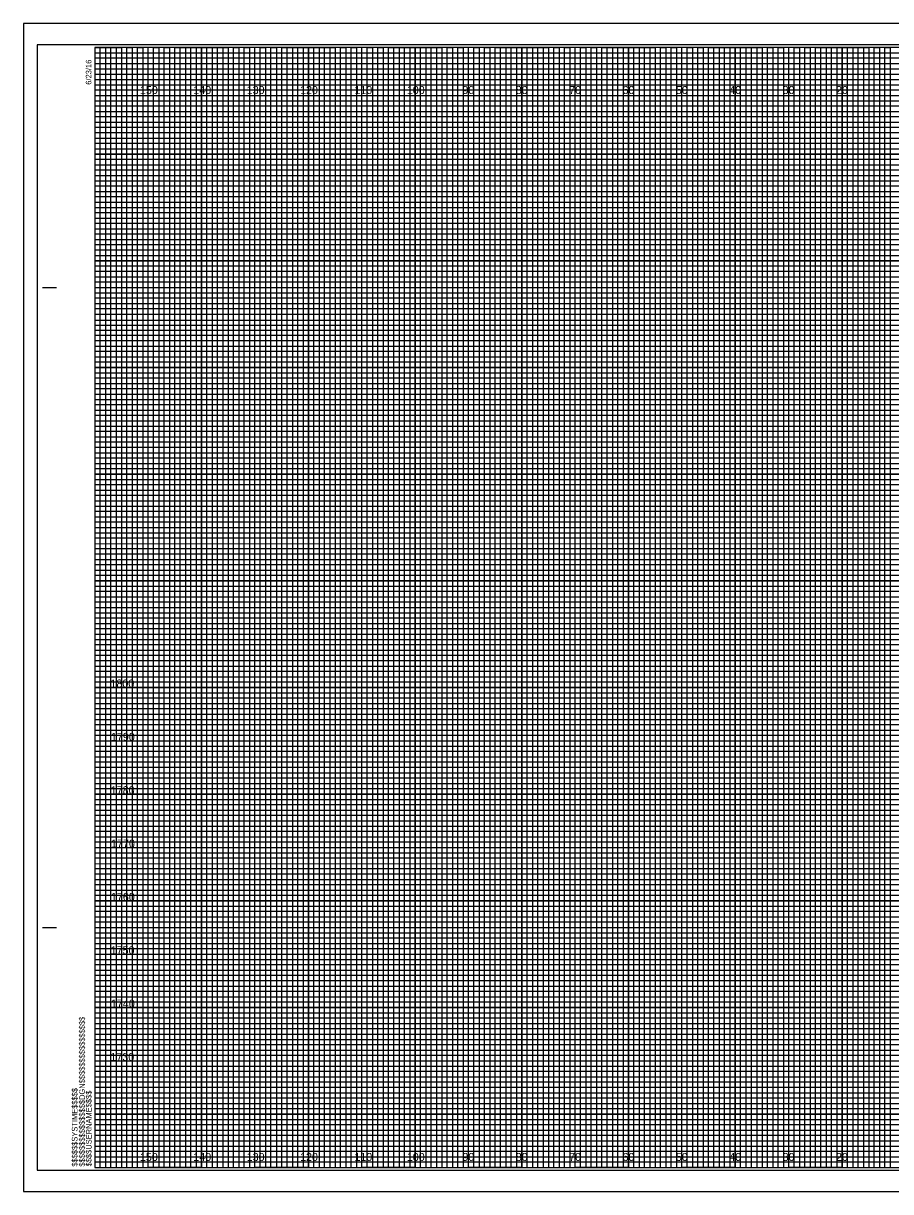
# Model space of a CAD drawing. Extents: x 570 to 907, y -9 to 870.
# Drawn here: x 570.4 to 732.9, y 650.6 to 869.6 of the extents above; entities that cross this region are included whole.
import ezdxf

# ---------------------------------------------------------------- set-up
doc = ezdxf.new("R2010")
doc.units = 0
for name, color, linetype in [('Prop XS Earthwork Shape', 7, 'Continuous'), ('Raster_Level_0', 7, 'Continuous'), ('Scratch_Level_3', 7, 'Continuous'), ('Sheet Cross Section CELL', 7, 'Continuous'), ('Sheet Cross Section Grid Middle CELL', 7, 'Continuous'), ('Sheet Cross Section Grid Minor 1 CELL', 7, 'Continuous'), ('Sheet Cross Section Grid Minor 2 CELL', 7, 'Continuous'), ('Sheet Cutting Line CELL', 7, 'Continuous'), ('Sheet DOT Grid CELL', 7, 'Continuous'), ('Sheet Plot Border Inside CELL', 7, 'Continuous'), ('Sheet Plot Border Outside CELL', 7, 'Continuous')]:
    doc.layers.add(name, color=color, linetype=linetype)

msp = doc.modelspace()

# ---------------------------------------------------------------- linework, layer by layer
at = {"layer": 'Prop XS Earthwork Shape'}
for p, q in [((593.77, 865.14), (583.77, 865.14)), ((593.77, 655.14), (593.77, 865.14)), ((613.77, 865.14), (603.77, 865.14)), ((603.77, 865.14), (603.77, 655.14)), ((613.77, 655.14), (613.77, 865.14)), ((633.77, 865.14), (623.77, 865.14)), ((623.77, 865.14), (623.77, 655.14)), ((633.77, 655.14), (633.77, 865.14)), ((653.77, 865.14), (643.77, 865.14)), ((643.77, 865.14), (643.77, 655.14)), ((653.77, 655.14), (653.77, 865.14)), ((673.77, 865.14), (663.77, 865.14)), ((663.77, 865.14), (663.77, 655.14)), ((673.77, 655.14), (673.77, 865.14)), ((693.77, 865.14), (683.77, 865.14)), ((683.77, 865.14), (683.77, 655.14)), ((693.77, 655.14), (693.77, 865.14)), ((713.77, 865.14), (703.77, 865.14)), ((703.77, 865.14), (703.77, 655.14)), ((713.77, 655.14), (713.77, 865.14)), ((733.77, 865.14), (723.77, 865.14)), ((723.77, 865.14), (723.77, 655.14)), ((603.77, 655.14), (593.77, 655.14)), ((623.77, 655.14), (613.77, 655.14)), ((643.77, 655.14), (633.77, 655.14)), ((663.77, 655.14), (653.77, 655.14)), ((683.77, 655.14), (673.77, 655.14)), ((703.77, 655.14), (693.77, 655.14)), ((723.77, 655.14), (713.77, 655.14))]:
    msp.add_line(p, q, dxfattribs=at)
for points in [[(583.77, 855.14), (903.77, 855.14), (903.77, 845.14), (583.77, 845.14)], [(583.77, 835.14), (903.77, 835.14), (903.77, 825.14), (583.77, 825.14)], [(583.77, 815.14), (903.77, 815.14), (903.77, 805.14), (583.77, 805.14)], [(583.77, 795.14), (903.77, 795.14), (903.77, 785.14), (583.77, 785.14)], [(583.77, 775.14), (903.77, 775.14), (903.77, 765.14), (583.77, 765.14)], [(583.77, 755.14), (903.77, 755.14), (903.77, 745.14), (583.77, 745.14)], [(583.77, 735.14), (903.77, 735.14), (903.77, 725.14), (583.77, 725.14)], [(583.77, 715.14), (903.77, 715.14), (903.77, 705.14), (583.77, 705.14)], [(583.77, 695.14), (903.77, 695.14), (903.77, 685.14), (583.77, 685.14)], [(583.77, 675.14), (903.77, 675.14), (903.77, 665.14), (583.77, 665.14)]]:
    msp.add_lwpolyline(points, dxfattribs=at)
at = {"layer": 'Sheet Cross Section CELL'}
for p, q in [((573.97, 820.14), (576.47, 820.14)), ((574.07, 820.14), (576.57, 820.14)), ((573.97, 700.14), (576.47, 700.14)), ((574.07, 700.14), (576.57, 700.14)), ((583.77, 655.14), (583.77, 655.14)), ((583.77, 655.14), (583.77, 655.14)), ((583.77, 655.14), (583.77, 655.14)), ((583.77, 655.14), (583.77, 655.14)), ((583.77, 655.14), (583.77, 655.14)), ((583.77, 655.14), (583.77, 655.14)), ((583.77, 655.14), (583.77, 655.14))]:
    msp.add_line(p, q, dxfattribs=at)
msp.add_lwpolyline([(903.77, 865.14), (583.77, 865.14), (583.77, 655.14), (903.77, 655.14)], close=True, dxfattribs=at)
at = {"layer": 'Sheet Cross Section Grid Middle CELL'}
for points in [[(583.77, 865.14), (588.77, 865.14), (588.77, 655.14), (598.77, 655.14), (598.77, 865.14), (608.77, 865.14), (608.77, 655.14), (618.77, 655.14), (618.77, 865.14), (628.77, 865.14), (628.77, 655.14), (638.77, 655.14), (638.77, 865.14), (648.77, 865.14), (648.77, 655.14), (658.77, 655.14), (658.77, 865.14), (668.77, 865.14), (668.77, 655.14), (678.77, 655.14), (678.77, 865.14), (688.77, 865.14), (688.77, 655.14), (698.77, 655.14), (698.77, 865.14), (708.77, 865.14), (708.77, 655.14), (718.77, 655.14), (718.77, 865.14), (728.77, 865.14), (728.77, 655.14), (738.77, 655.14)], [(583.77, 860.14), (858.77, 860.14)], [(583.77, 840.14), (903.77, 840.14), (903.77, 850.14), (583.77, 850.14)], [(583.77, 820.14), (903.77, 820.14), (903.77, 830.14), (583.77, 830.14)], [(583.77, 800.14), (903.77, 800.14), (903.77, 810.14), (583.77, 810.14)], [(583.77, 780.14), (903.77, 780.14), (903.77, 790.14), (583.77, 790.14)], [(583.77, 760.14), (903.77, 760.14), (903.77, 770.14), (583.77, 770.14)], [(583.77, 740.14), (903.77, 740.14), (903.77, 750.14), (583.77, 750.14)], [(583.77, 720.14), (903.77, 720.14), (903.77, 730.14), (583.77, 730.14)], [(583.77, 700.14), (903.77, 700.14), (903.77, 710.14), (583.77, 710.14)], [(583.77, 680.14), (903.77, 680.14), (903.77, 690.14), (583.77, 690.14)], [(583.77, 660.14), (903.77, 660.14), (903.77, 670.14), (583.77, 670.14)]]:
    msp.add_lwpolyline(points, dxfattribs=at)
at = {"layer": 'Sheet Cross Section Grid Minor 1 CELL'}
for p, q in [((583.77, 864.14), (843.77, 864.14)), ((843.77, 863.12), (583.77, 863.12)), ((583.77, 863.12), (583.77, 862.14)), ((583.77, 862.14), (843.77, 862.14)), ((843.77, 861.03), (583.77, 861.03)), ((583.77, 861.03), (583.77, 859.14)), ((583.77, 859.14), (903.77, 859.14))]:
    msp.add_line(p, q, dxfattribs=at)
for points in [[(583.77, 858.14), (853.77, 858.14), (903.77, 858.14), (903.77, 857.14), (583.77, 857.14)], [(583.77, 856.14), (903.77, 856.14), (903.77, 854.14), (583.77, 854.14)], [(583.77, 853.14), (903.77, 853.14), (903.77, 852.14), (583.77, 852.12)], [(583.77, 851.14), (903.77, 851.14), (903.77, 849.14), (583.77, 849.14)], [(583.77, 848.14), (903.77, 848.14), (903.77, 847.14), (583.77, 847.14)], [(583.77, 846.14), (903.77, 846.14), (903.77, 844.14), (583.77, 844.14)], [(583.77, 843.14), (903.77, 843.14), (903.77, 842.14), (583.77, 842.14)], [(583.77, 841.14), (903.77, 841.14), (903.77, 839.14), (583.77, 839.14)], [(583.77, 838.14), (903.77, 838.14), (903.77, 837.14), (583.77, 837.14)], [(583.77, 836.14), (903.77, 836.14), (903.77, 834.14), (583.77, 834.14)], [(583.77, 833.14), (903.77, 833.14), (903.77, 832.14), (583.77, 832.14)], [(583.77, 831.14), (903.77, 831.14), (903.77, 829.09), (903.77, 828.14), (903.77, 827.14), (583.77, 827.14)], [(583.77, 829.14), (903.77, 829.14), (903.77, 828.14), (583.77, 828.14)], [(583.77, 826.14), (903.77, 826.14), (903.77, 824.14), (583.77, 824.17)], [(583.77, 824.17), (903.77, 824.14), (903.77, 823.14), (583.77, 823.14)], [(583.77, 822.14), (903.77, 822.14), (903.77, 821.14), (583.77, 821.14)], [(583.77, 819.14), (903.77, 819.14), (903.77, 818.14), (583.77, 818.14)], [(583.77, 817.14), (903.77, 817.14), (903.77, 816.14), (583.77, 816.14)], [(583.7, 814.03), (903.77, 814.03), (903.77, 813.02), (583.7, 813.02)], [(583.77, 812.14), (903.77, 812.14), (903.77, 811.14), (583.77, 811.14)], [(583.77, 809.14), (903.77, 809.14), (903.77, 808.14), (583.77, 808.14)], [(583.77, 807.14), (903.77, 807.14), (903.77, 806.14), (583.77, 806.14)], [(583.77, 804.14), (903.77, 804.14), (903.77, 803.14), (583.77, 803.14)], [(583.77, 802.14), (903.77, 802.14), (903.77, 801.14), (583.77, 801.14)], [(583.77, 799.14), (903.77, 799.14), (903.77, 798.14), (583.77, 798.14)], [(583.77, 797.14), (903.77, 797.14), (903.77, 796.14), (583.77, 796.14)], [(583.77, 794.14), (903.77, 794.14), (903.76, 793.12), (583.77, 793.14)], [(583.77, 792.14), (903.77, 792.14), (903.77, 791.14), (583.77, 791.14)], [(583.77, 789.14), (903.77, 789.14), (903.77, 788.14), (583.77, 788.14)], [(583.77, 787.14), (903.77, 787.14), (903.77, 786.14), (583.77, 786.14)], [(583.77, 784.14), (903.77, 784.14), (903.77, 783.14), (583.77, 783.14)], [(583.77, 782.14), (903.77, 782.14), (903.77, 781.14), (583.77, 781.14)], [(583.77, 779.14), (903.77, 779.14), (903.77, 778.14), (583.77, 778.14)], [(583.77, 777.14), (903.77, 777.14), (903.77, 776.14), (583.77, 776.14)], [(583.77, 774.14), (903.77, 774.14), (903.77, 773.14), (583.77, 773.14)], [(583.77, 772.13), (903.84, 772.05), (903.77, 771.14), (583.77, 771.14)], [(583.77, 769.14), (903.77, 769.14), (903.77, 768.14), (583.77, 768.14)], [(583.77, 767.14), (903.77, 767.14), (903.77, 766.14), (583.77, 766.14)], [(583.77, 764.14), (903.77, 764.14), (903.77, 763.14), (583.77, 763.14)], [(583.77, 762.14), (903.77, 762.14), (903.77, 761.14), (583.77, 761.14)], [(583.77, 759.14), (903.77, 759.14), (903.77, 758.14), (583.77, 758.14)], [(583.77, 757.14), (903.77, 757.14), (903.77, 756.14), (583.77, 756.14)], [(583.77, 754.14), (903.77, 754.14), (903.77, 753.14), (583.77, 753.14)], [(583.77, 752.14), (903.77, 752.14), (903.77, 751.14), (583.77, 751.14)], [(583.77, 749.14), (903.77, 749.14), (903.77, 748.14), (583.77, 748.14)], [(583.77, 747.14), (903.77, 747.14), (903.77, 746.14), (583.77, 746.14)], [(583.77, 744.14), (903.77, 744.14), (903.77, 743.14), (583.77, 743.14)], [(583.77, 742.14), (903.77, 742.14), (903.77, 741.14), (583.77, 741.14)], [(583.77, 739.14), (903.77, 739.14), (903.77, 738.14), (583.77, 738.14)], [(583.77, 737.14), (903.77, 737.14), (903.77, 736.14), (583.77, 736.14)], [(583.77, 734.14), (903.77, 734.14), (903.76, 733.12), (583.77, 733.14)], [(583.77, 732.14), (903.77, 732.14), (903.77, 731.14), (583.77, 731.14)], [(583.77, 729.14), (903.77, 729.14), (903.77, 728.14), (583.77, 728.14)], [(583.77, 727.14), (903.77, 727.14), (903.77, 726.14), (583.77, 726.14)], [(583.77, 724.14), (903.77, 724.14), (903.77, 723.14), (583.77, 723.14)], [(583.77, 722.14), (903.77, 722.14), (903.77, 721.14), (583.77, 721.14)], [(583.77, 719.14), (903.77, 719.14), (903.77, 718.14), (583.77, 718.14)], [(583.77, 717.14), (903.77, 717.14), (903.77, 716.14), (583.77, 716.14)], [(583.77, 714.14), (903.77, 714.14), (903.77, 713.14), (583.77, 713.14)], [(583.77, 712.13), (903.84, 712.05), (903.77, 711.14), (583.77, 711.14)], [(583.77, 709.14), (903.77, 709.14), (903.77, 708.14), (583.77, 708.14)], [(583.77, 707.14), (903.77, 707.14), (903.77, 706.14), (583.77, 706.14)], [(583.77, 704.14), (903.77, 704.14), (903.77, 703.14), (583.77, 703.14)], [(583.77, 702.14), (903.77, 702.14), (903.77, 701.14), (583.77, 701.14)], [(583.77, 699.14), (903.77, 699.14), (903.77, 698.14), (583.77, 698.14)], [(583.77, 697.14), (903.77, 697.14), (903.77, 696.14), (583.77, 696.14)], [(583.77, 694.14), (903.77, 694.14), (903.77, 693.14), (583.77, 693.14)], [(583.77, 692.14), (903.77, 692.14), (903.77, 691.14), (583.77, 691.14)], [(583.77, 689.14), (903.77, 689.14), (903.77, 688.14), (583.77, 688.14)], [(583.77, 687.14), (903.77, 687.14), (903.77, 686.14), (583.77, 686.14)], [(583.77, 684.14), (903.77, 684.14), (903.77, 683.14), (583.77, 683.14)], [(583.77, 682.14), (903.77, 682.14), (903.77, 681.14), (583.77, 681.14)], [(583.77, 679.14), (903.77, 679.14), (903.77, 678.14), (583.77, 678.14)], [(583.77, 677.14), (903.77, 677.14), (903.77, 676.14), (583.77, 676.14)], [(583.77, 674.14), (903.77, 674.14), (903.77, 673.14), (583.77, 673.14)], [(583.77, 672.14), (903.77, 672.14), (903.77, 671.14), (583.77, 671.14)], [(583.77, 669.14), (903.77, 669.14), (903.77, 668.14), (583.77, 668.14)], [(583.77, 667.14), (903.77, 667.14), (903.77, 666.14), (583.77, 666.14)], [(583.77, 664.14), (903.77, 664.14), (903.77, 663.14), (583.77, 663.14)], [(583.77, 662.14), (903.77, 662.14), (903.77, 661.14), (583.77, 661.14)], [(583.77, 659.14), (903.77, 659.14), (903.77, 658.14), (583.77, 658.14)], [(583.77, 657.14), (903.77, 657.14), (903.77, 656.14), (583.77, 656.14)]]:
    msp.add_lwpolyline(points, dxfattribs=at)
at = {"layer": 'Sheet Cross Section Grid Minor 2 CELL'}
for points in [[(583.77, 655.14), (584.77, 655.14), (584.77, 865.14), (585.77, 865.14), (585.77, 655.14)], [(585.77, 655.14), (586.77, 655.14), (586.77, 865.14), (587.77, 865.14), (587.77, 655.14)], [(588.77, 655.14), (589.77, 655.14), (589.77, 865.14), (590.77, 865.14), (590.77, 655.14)], [(590.77, 655.14), (591.77, 655.14), (591.77, 865.14), (592.77, 865.14), (592.77, 655.14)], [(593.77, 655.14), (594.77, 655.14), (594.77, 865.14), (595.77, 865.14), (595.77, 655.14)], [(595.77, 655.14), (596.77, 655.14), (596.77, 865.14), (597.77, 865.14), (597.77, 655.14)], [(598.77, 655.14), (599.77, 655.14), (599.77, 865.14), (600.77, 865.14), (600.77, 655.14)], [(600.77, 655.14), (601.77, 655.14), (601.77, 865.14), (602.77, 865.14), (602.77, 655.14)], [(603.77, 655.14), (604.77, 655.14), (604.77, 865.14), (605.77, 865.14), (605.77, 655.14)], [(605.77, 655.14), (606.77, 655.14), (606.77, 865.14), (607.77, 865.14), (607.77, 655.14)], [(608.77, 655.14), (609.77, 655.14), (609.77, 865.14), (610.77, 865.14), (610.77, 655.14)], [(610.77, 655.14), (611.77, 655.14), (611.77, 865.14), (612.77, 865.14), (612.77, 655.14)], [(613.77, 655.14), (614.77, 655.14), (614.77, 865.14), (615.77, 865.14), (615.77, 655.14)], [(615.77, 655.14), (616.77, 655.14), (616.77, 865.14), (617.77, 865.14), (617.77, 655.14)], [(618.77, 655.14), (619.77, 655.14), (619.77, 865.14), (620.77, 865.14), (620.77, 655.14)], [(620.77, 655.14), (621.77, 655.14), (621.77, 865.14), (622.77, 865.14), (622.77, 655.14)], [(623.77, 655.14), (624.77, 655.14), (624.77, 865.14), (625.77, 865.14), (625.77, 655.14)], [(625.77, 655.14), (626.77, 655.14), (626.77, 865.14), (627.77, 865.14), (627.77, 655.14)], [(628.77, 655.14), (629.77, 655.14), (629.77, 865.14), (630.77, 865.14), (630.77, 655.14)], [(630.77, 655.14), (631.77, 655.14), (631.77, 865.14), (632.77, 865.14), (632.77, 655.14)], [(633.77, 655.14), (634.77, 655.14), (634.77, 865.14), (635.77, 865.14), (635.77, 655.14)], [(635.77, 655.14), (636.77, 655.14), (636.77, 865.14), (637.77, 865.14), (637.77, 655.14)], [(638.77, 655.14), (639.77, 655.14), (639.77, 865.14), (640.77, 865.14), (640.77, 655.14)], [(640.77, 655.14), (641.77, 655.14), (641.77, 865.14), (642.77, 865.14), (642.77, 655.14)], [(643.77, 655.14), (644.77, 655.14), (644.77, 865.14), (645.77, 865.14), (645.77, 655.14)], [(645.77, 655.14), (646.77, 655.14), (646.77, 865.14), (647.77, 865.14), (647.77, 655.14)], [(648.77, 655.14), (649.77, 655.14), (649.77, 865.14), (650.77, 865.14), (650.77, 655.14)], [(650.77, 655.14), (651.77, 655.14), (651.77, 865.14), (652.77, 865.14), (652.77, 655.14)], [(653.77, 655.14), (654.77, 655.14), (654.77, 865.14), (655.77, 865.14), (655.77, 655.14)], [(655.77, 655.14), (656.77, 655.14), (656.77, 865.14), (657.77, 865.14), (657.77, 655.14)], [(658.77, 655.14), (659.77, 655.14), (659.77, 865.14), (660.77, 865.14), (660.77, 655.14)], [(660.77, 655.14), (661.77, 655.14), (661.77, 865.14), (662.77, 865.14), (662.77, 655.14)], [(663.77, 655.14), (664.77, 655.14), (664.77, 865.14), (665.77, 865.14), (665.77, 655.14)], [(665.77, 655.14), (666.77, 655.14), (666.77, 865.14), (667.77, 865.14), (667.77, 655.14)], [(668.77, 655.14), (669.77, 655.14), (669.77, 865.14), (670.77, 865.14), (670.77, 655.14)], [(670.77, 655.14), (671.77, 655.14), (671.77, 865.14), (672.77, 865.14), (672.77, 655.14)], [(673.77, 655.14), (674.77, 655.14), (674.77, 865.14), (675.77, 865.14), (675.77, 655.14)], [(675.77, 655.14), (676.77, 655.14), (676.77, 865.14), (677.77, 865.14), (677.77, 655.14)], [(678.77, 655.14), (679.77, 655.14), (679.77, 865.14), (680.77, 865.14), (680.77, 655.14)], [(680.77, 655.14), (681.77, 655.14), (681.77, 865.14), (682.77, 865.14), (682.77, 655.14)], [(683.77, 655.14), (684.77, 655.14), (684.77, 865.14), (685.77, 865.14), (685.77, 655.14)], [(685.77, 655.14), (686.77, 655.14), (686.77, 865.14), (687.77, 865.14), (687.77, 655.14)], [(688.77, 655.14), (689.77, 655.14), (689.77, 865.14), (690.77, 865.14), (690.77, 655.14)], [(690.77, 655.14), (691.77, 655.14), (691.77, 865.14), (692.77, 865.14), (692.77, 655.14)], [(693.77, 655.14), (694.77, 655.14), (694.77, 865.14), (695.77, 865.14), (695.77, 655.14)], [(695.77, 655.14), (696.77, 655.14), (696.77, 865.14), (697.77, 865.14), (697.77, 655.14)], [(698.77, 655.14), (699.77, 655.14), (699.77, 865.14), (700.77, 865.14), (700.77, 655.14)], [(700.77, 655.14), (701.77, 655.14), (701.77, 865.14), (702.77, 865.14), (702.77, 655.14)], [(703.77, 655.14), (704.77, 655.14), (704.77, 865.14), (705.77, 865.14), (705.77, 655.14)], [(705.77, 655.14), (706.77, 655.14), (706.77, 865.14), (707.77, 865.14), (707.77, 655.14)], [(708.77, 655.14), (709.77, 655.14), (709.77, 865.14), (710.77, 865.14), (710.77, 655.14)], [(710.77, 655.14), (711.77, 655.14), (711.77, 865.14), (712.77, 865.14), (712.77, 655.14)], [(713.77, 655.14), (714.77, 655.14), (714.77, 865.14), (715.77, 865.14), (715.77, 655.14)], [(715.77, 655.14), (716.77, 655.14), (716.77, 865.14), (717.77, 865.14), (717.77, 655.14)], [(718.77, 655.14), (719.77, 655.14), (719.77, 865.14), (720.77, 865.14), (720.77, 655.14)], [(720.77, 655.14), (721.77, 655.14), (721.77, 865.14), (722.77, 865.14), (722.77, 655.14)], [(723.77, 655.14), (724.77, 655.14), (724.77, 865.14), (725.77, 865.14), (725.77, 655.14)], [(725.77, 655.14), (726.77, 655.14), (726.77, 865.14), (727.77, 865.14), (727.77, 655.14)], [(728.77, 655.14), (729.77, 655.14), (729.77, 865.14), (730.77, 865.14), (730.77, 655.14)], [(730.77, 655.14), (731.77, 655.14), (731.77, 865.14), (732.77, 865.14), (732.77, 655.14)]]:
    msp.add_lwpolyline(points, dxfattribs=at)
at = {"layer": 'Sheet Cutting Line CELL'}
for p, q in [((907.07, 869.64), (570.37, 869.64)), ((570.37, 869.64), (570.37, 650.64)), ((570.37, 650.64), (907.07, 650.64))]:
    msp.add_line(p, q, dxfattribs=at)
at = {"layer": 'Sheet DOT Grid CELL'}
for p, q in [((593.77, 655.14), (593.77, 865.14)), ((603.77, 655.14), (603.77, 865.14)), ((613.77, 655.14), (613.77, 865.14)), ((623.77, 655.14), (623.77, 865.14)), ((633.77, 655.14), (633.77, 865.14)), ((643.77, 655.14), (643.77, 865.14)), ((653.77, 655.14), (653.77, 865.14)), ((663.77, 655.14), (663.77, 865.14)), ((673.77, 655.14), (673.77, 865.14)), ((683.77, 655.14), (683.77, 865.14)), ((693.77, 655.14), (693.77, 865.14)), ((703.77, 655.14), (703.77, 865.14)), ((713.77, 655.14), (713.77, 865.14)), ((723.77, 655.14), (723.77, 865.14)), ((583.77, 855.14), (903.77, 855.14)), ((583.77, 845.14), (903.77, 845.14)), ((583.77, 835.14), (903.77, 835.14)), ((583.77, 825.14), (903.77, 825.14)), ((583.77, 815.14), (903.77, 815.14)), ((583.77, 805.14), (903.77, 805.14)), ((583.77, 795.14), (903.77, 795.14)), ((583.77, 785.14), (903.77, 785.14)), ((583.77, 775.14), (903.77, 775.14)), ((583.77, 765.14), (903.77, 765.14)), ((583.77, 755.14), (903.77, 755.14)), ((583.77, 745.14), (903.77, 745.14)), ((583.77, 735.14), (903.77, 735.14)), ((583.77, 725.14), (903.77, 725.14)), ((583.77, 715.14), (903.77, 715.14)), ((583.77, 705.14), (903.77, 705.14)), ((583.77, 695.14), (903.77, 695.14)), ((583.77, 685.14), (903.77, 685.14)), ((583.77, 675.14), (903.77, 675.14)), ((583.77, 665.14), (903.77, 665.14))]:
    msp.add_line(p, q, dxfattribs=at)
at = {"layer": 'Sheet Plot Border Inside CELL'}
msp.add_lwpolyline([(572.97, 654.64), (906.17, 654.64), (906.17, 865.64), (572.97, 865.64)], close=True, dxfattribs=at)
at = {"layer": 'Sheet Plot Border Outside CELL'}
msp.add_lwpolyline([(570.37, 650.64), (907.07, 650.64), (907.07, 869.64), (570.37, 869.64)], close=True, dxfattribs=at)

# ---------------------------------------------------------------- texts
at = {"layer": 'Raster_Level_0'}
for s, p in [('150', (592.22, 856.39)), ('140', (602.22, 856.39)), ('130', (612.22, 856.39)), ('120', (622.22, 856.39)), ('110', (632.4, 856.39)), ('100', (642.22, 856.39)), ('90', (652.63, 856.39)), ('80', (662.63, 856.39)), ('70', (672.63, 856.39)), ('60', (682.63, 856.39)), ('50', (692.63, 856.39)), ('40', (702.63, 856.39)), ('30', (712.63, 856.39)), ('20', (722.63, 856.39)), ('150', (592.22, 656.39)), ('140', (602.22, 656.39)), ('130', (612.22, 656.39)), ('120', (622.22, 656.39)), ('110', (632.4, 656.39)), ('100', (642.22, 656.39)), ('90', (652.63, 656.39)), ('80', (662.63, 656.39)), ('70', (672.63, 656.39)), ('60', (682.63, 656.39)), ('50', (692.63, 656.39)), ('40', (702.63, 656.39)), ('30', (712.63, 656.39)), ('20', (722.63, 656.39))]:
    msp.add_text(s, height=1.5, dxfattribs=at).set_placement(p)
at = {"layer": 'Scratch_Level_3'}
for s, p in [('1800', (586.69, 745.14)), ('1790', (586.78, 735.14)), ('1780', (586.75, 725.14)), ('1770', (586.81, 715.14)), ('1760', (586.78, 705.14)), ('1750', (586.73, 695.14)), ('1740', (586.78, 685.14)), ('1730', (586.69, 675.14))]:
    msp.add_text(s, height=1.5, dxfattribs=at).set_placement(p)
at = {"layer": 'Sheet Cross Section CELL'}
for s, p in [('6/23/16', (583.12, 858.14)), ('$$$$$$$$$$$$$$$$DGN$$$$$$$$$$$$$$$$', (581.89, 655.32)), ('$$$$$$SYSTIME$$$$$', (580.51, 655.32)), ('$$$$USERNAME$$$$', (583.15, 655.37))]:
    msp.add_text(s, height=1.05, rotation=90, dxfattribs=at).set_placement(p)

doc.saveas('drawing.dxf')
